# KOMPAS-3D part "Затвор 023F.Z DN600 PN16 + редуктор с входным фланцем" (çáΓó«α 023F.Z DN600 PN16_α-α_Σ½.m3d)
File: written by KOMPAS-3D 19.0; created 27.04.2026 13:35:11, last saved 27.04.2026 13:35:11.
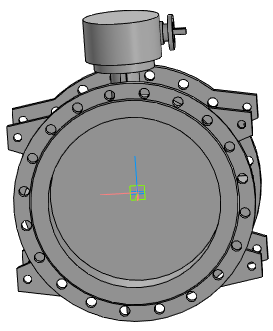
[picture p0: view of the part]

Document properties: Полное имя файла: ..\..\Затвор 023F.Z DN200-DN1600_редуктор с входным фланцем\Затвор 023F.Z DN600 PN16 + редуктор с входным фланцем.a3d

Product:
- Part/product: Затвор 023F.Z DN600 PN16 + редуктор с входным фланцем
    Масса: 475.445

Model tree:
1. Операция без истории:1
